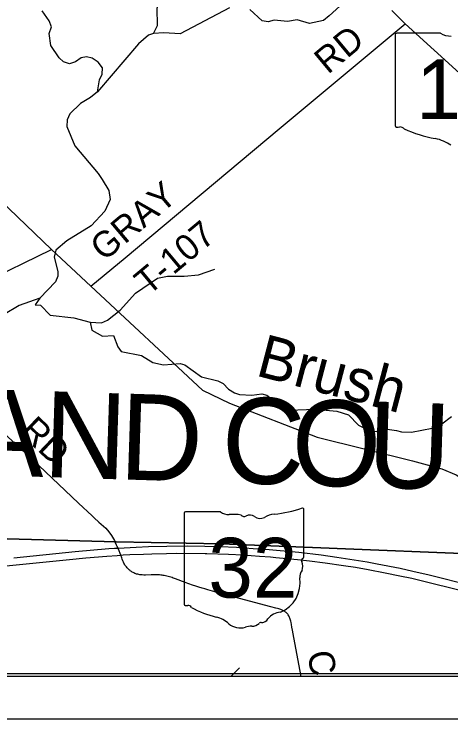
# Model space of a CAD drawing. Extents: x 0 to 34, y 0 to 22.
# Drawn here: x 3.558 to 4.521, y 14 to 15.554 of the extents above; entities that cross this region are included whole.
import ezdxf

# ---------------------------------------------------------------- set-up
doc = ezdxf.new("R2010")
doc.units = 0
for name, color, linetype in [('Default', 7, 'Continuous'), ('GM_X_County_Text', 7, 'Continuous'), ('GM_X_Minor_River', 7, 'Continuous'), ('GM_X_Minor_River_Text', 7, 'Continuous'), ('GM_X_State_Location', 7, 'Continuous'), ('GM_X_State_Route', 7, 'Continuous'), ('GM_X_State_Shield', 7, 'Continuous'), ('GM_X_Township_Road', 7, 'Continuous'), ('GM_X_Township_Road_Text', 7, 'Continuous'), ('SH_Cut_Line', 7, 'Continuous'), ('SH_Data', 7, 'Continuous')]:
    doc.layers.add(name, color=color, linetype=linetype)

msp = doc.modelspace()

# ---------------------------------------------------------------- linework, layer by layer
at = {"layer": 'Default'}
msp.add_lwpolyline([(2.3212, 18.6531), (2.2797, 17.8302), (2.2668, 17.0936), (2.2632, 16.8811), (2.258, 16.7775), (2.1837, 15.746), (2.1, 14.637), (2.1, 14.4457), (2.4012, 14.4298), (2.4436, 14.4284), (2.5802, 14.4232), (3.783, 14.3901), (4.0144, 14.3862), (4.819, 14.3535), (4.9366, 14.3421), (5.2368, 14.8438), (5.4205, 15.1508), (5.9071, 15.964)], dxfattribs=at)
msp.add_lwpolyline([(2.1, 14.4457), (2.1, 14.243), (2.102, 14.2411), (2.1319, 14.2168), (2.1359, 14.2103), (2.1425, 14.1753), (2.1455, 14.1482), (2.1436, 14.1288), (2.1399, 14.114), (2.1382, 14.1043), (2.1342, 14.0941), (7.3096, 14.0941), (7.3204, 14.3032), (6.8864, 14.3056), (6.7418, 14.3069), (5.4793, 14.3187), (5.0616, 14.3309), (4.9366, 14.3421), (4.819, 14.3535), (4.0144, 14.3862), (3.783, 14.3901), (2.5802, 14.4232), (2.4436, 14.4284), (2.4012, 14.4298)], close=True, dxfattribs=at)
at = {"layer": 'GM_X_Minor_River'}
for points in [[(3.8652, 15.5114), (3.8742, 15.5291), (3.8735, 15.5674), (3.8875, 15.6149), (3.8984, 15.6641), (3.9138, 15.6855), (3.9254, 15.6982), (3.9309, 15.7114), (3.9227, 15.7778), (3.9304, 15.7906), (3.9449, 15.798), (3.9692, 15.8226), (4.0016, 15.8385), (4.015, 15.8436)], [(4.276, 15.5716), (4.2526, 15.55), (4.2396, 15.5399), (4.2091, 15.5332), (4.1819, 15.5416), (4.1603, 15.5377), (4.1315, 15.5408), (4.1178, 15.5372), (4.1049, 15.5389), (4.0772, 15.564)], [(4.0329, 15.5681), (3.924, 15.5105), (3.888, 15.5129), (3.8652, 15.5114), (3.8541, 15.5077), (3.8319, 15.4884), (3.7417, 15.3823), (3.7267, 15.37), (3.7045, 15.3567), (3.681, 15.3339), (3.6748, 15.3207), (3.6742, 15.306), (3.6922, 15.2636), (3.743, 15.2022), (3.7523, 15.1891), (3.7671, 15.165), (3.7695, 15.1453), (3.7582, 15.1196), (3.7281, 15.0871), (3.6742, 15.0541), (3.65, 15.0336), (3.6463, 15.0181), (3.6543, 14.9861), (3.6545, 14.9762), (3.6494, 14.9634), (3.6147, 14.9279), (3.5694, 14.9114), (3.5346, 14.8907)], [(3.7417, 15.3823), (3.7464, 15.4094), (3.7523, 15.4214), (3.7529, 15.4354), (3.7429, 15.4481), (3.7298, 15.4567), (3.7177, 15.4599), (3.7055, 15.4575), (3.6932, 15.4486), (3.6799, 15.4443), (3.6671, 15.4491), (3.657, 15.4572), (3.6389, 15.4845), (3.6355, 15.5115), (3.6403, 15.5258), (3.6356, 15.5395), (3.6201, 15.5614)], [(3.6147, 14.9279), (3.6043, 14.9132), (3.6164, 14.9123), (3.6378, 14.8904), (3.6893, 14.8843), (3.7256, 14.8751), (3.7506, 14.8736), (3.7636, 14.8791), (3.7916, 14.9014), (3.8258, 14.9385), (3.8741, 14.9719), (3.8962, 14.9761), (3.933, 14.9764), (3.9645, 14.9789), (4.0003, 14.9917)], [(3.7256, 14.8751), (3.7291, 14.8572), (3.7525, 14.8439), (3.7768, 14.8451), (3.7867, 14.8207), (3.7941, 14.8103), (3.8387, 14.801), (3.864, 14.7858), (3.8874, 14.7809), (3.9242, 14.7834), (3.9341, 14.781), (3.9713, 14.7539), (4.0068, 14.7454), (4.0189, 14.7395), (4.0308, 14.7269), (4.0436, 14.7187), (4.0546, 14.7155), (4.0819, 14.714), (4.1039, 14.7167), (4.1149, 14.7139), (4.1505, 14.6864), (4.1641, 14.6805), (4.2218, 14.6831), (4.2691, 14.6782), (4.2952, 14.6702), (4.3173, 14.6479), (4.3406, 14.6362), (4.3557, 14.6337), (4.3752, 14.6394), (4.4005, 14.6356), (4.4115, 14.6332), (4.4342, 14.6321), (4.4795, 14.6413), (4.5008, 14.6508), (4.5219, 14.6668)], [(4.0364, 14.0941), (4.0453, 14.1028), (4.0549, 14.1129)]]:
    msp.add_lwpolyline(points, dxfattribs=at)
at = {"layer": 'GM_X_State_Route'}
for points in [[(5.4443, 14.4648), (5.2846, 14.7184), (5.2371, 14.8433), (5.0427, 14.9665), (4.4202, 15.5326), (4.3908, 15.5621)], [(3.5576, 14.3555), (3.6924, 14.369), (3.7667, 14.3756), (3.779, 14.3764), (3.787, 14.3768), (3.8002, 14.3775), (3.827, 14.3788), (3.8543, 14.38), (3.8948, 14.3809), (3.9396, 14.3813), (3.9781, 14.3808), (4.0125, 14.38), (4.0483, 14.3784), (4.0846, 14.3758), (4.1202, 14.3732), (4.1859, 14.3673), (4.2347, 14.3616), (4.2693, 14.3569), (4.2976, 14.3525), (4.3362, 14.3461), (4.3581, 14.3421), (4.4087, 14.332), (4.4366, 14.326), (4.4729, 14.3177), (4.5025, 14.3105), (4.5368, 14.3017)], [(3.496, 14.3328), (3.5627, 14.3397), (3.6066, 14.3441), (3.6802, 14.3514), (3.7161, 14.355), (3.7623, 14.3589), (3.7854, 14.3606), (3.7929, 14.361), (3.7987, 14.3614), (3.8134, 14.3622), (3.8432, 14.3635), (3.8612, 14.3643), (3.8942, 14.365), (3.9165, 14.3651), (3.9788, 14.3647)], [(3.9788, 14.3647), (3.9828, 14.3647), (4.0307, 14.3631), (4.0618, 14.3614), (4.0991, 14.3591), (4.1233, 14.3572), (4.1351, 14.3562), (4.1827, 14.3516), (4.2093, 14.3487), (4.2438, 14.3441), (4.2838, 14.3385), (4.3102, 14.3343), (4.3384, 14.3294), (4.3756, 14.3223), (4.4085, 14.3158), (4.4346, 14.3101), (4.4643, 14.3031), (4.5384, 14.2845)]]:
    msp.add_lwpolyline(points, dxfattribs=at)
at = {"layer": 'GM_X_State_Shield'}
for p, q in [((4.4978, 15.5118), (4.4013, 15.5118)), ((4.398, 15.5084), (4.398, 15.3082)), ((3.933, 14.4534), (3.933, 14.2532)), ((4.0128, 14.4568), (3.9355, 14.4568)), ((4.1966, 14.3571), (4.1966, 14.4618)), ((4.1966, 14.3571), (4.1966, 14.3571))]:
    msp.add_line(p, q, dxfattribs=at)
for centre, radius, start, end in [((3.936, 14.4538), 0.00305, 98.1301, 188.1301), ((4.0312, 14.48), 0.0296, 231.6195, 271.1119), ((4.1027, 14.7296), 0.2796, 275.8445, 288.9065), ((4.1937, 14.4622), 0.00294, 351.8621, 97.738), ((4.041, 14.3445), 0.1064, 80.4867, 94.9883), ((4.0651, 14.4548), 0.00855, 219.7921, 297.1024), ((4.0777, 14.4317), 0.0178, 54.4667, 119.1411), ((4.1006, 14.4634), 0.0214, 233.8562, 294.8282), ((4.1384, 14.3957), 0.0563, 97.3462, 120.7689), ((4.1959, 14.3494), 0.00454, 107.944, 210.337), ((4.167, 14.3362), 0.0273, 340.033, 23.6496), ((4.1935, 14.3567), 0.00314, 289.6038, 7.7341), ((4.2071, 14.3133), 0.0198, 136.8065, 186.9296), ((4.1184, 14.3), 0.0699, 292.3089, 8.9858), ((3.936, 14.2528), 0.00308, 171.9584, 258.3066), ((3.9365, 14.2733), 0.0235, 267.339, 280.6039), ((3.9413, 14.2417), 0.00848, 29.7484, 93.2717), ((4.0483, 14.4215), 0.2019, 240.4129, 257.1985), ((4.1479, 14.1971), 0.0383, 94.4031, 142.5768), ((3.9881, 14.1633), 0.0632, 47.1842, 75.836), ((4.0993, 14.2338), 0.0226, 282.8732, 323.2771), ((4.0565, 14.2407), 0.0401, 230.7004, 286.2918), ((4.0796, 14.1715), 0.0329, 85.6951, 111.2099), ((4.0826, 14.2257), 0.0214, 268.777, 315.5493), ((4.1019, 14.2063), 0.00601, 65.7517, 132.6484)]:
    msp.add_arc(centre, radius, start, end, dxfattribs=at)
for centre, major_axis, start_param, end_param in [((4.4018, 15.5088), (0.00382, 0), 1.712693, 3.28349), ((4.5208, 15.535), (0.037, 0), 4.042523, 4.731795), ((4.4019, 15.3078), (0.00385, 0), 3.00124, 4.508301), ((4.4024, 15.3283), (0.0294, 0), 4.665946, 4.897461), ((4.4085, 15.2967), (0.0106, 0), 0.519207, 1.627899), ((4.5423, 15.4765), (0.2524, 0), 4.195997, 4.488961), ((4.467, 15.2183), (0.079, 0), 0.823519, 1.323587)]:
    msp.add_ellipse(centre, major_axis=major_axis, ratio=0.8, start_param=start_param, end_param=end_param, dxfattribs=at)
at = {"layer": 'GM_X_Township_Road'}
msp.add_line((3.6407, 15.0353), (3.7273, 14.9544), dxfattribs=at)
for points in [[(3.1089, 15.5997), (3.1076, 15.5982), (3.1001, 15.5922), (3.0941, 15.5874), (3.0864, 15.5796), (3.0829, 15.5732), (3.0824, 15.5695), (3.0899, 15.5602), (3.2729, 15.3876), (3.4334, 15.2332), (3.6407, 15.0353)], [(3.7273, 14.9544), (3.8025, 15.0169), (4.1423, 15.3007), (4.4202, 15.5326)], [(2.5609, 14.9423), (2.8396, 14.8806), (2.9351, 14.891), (2.9697, 14.8931), (3.0011, 14.9073), (3.0233, 14.9153), (3.0404, 14.915), (3.1265, 14.9063), (3.1489, 14.9066), (3.2701, 14.9322), (3.3601, 14.9452), (3.3946, 14.9501), (3.4676, 14.9541), (3.4863, 14.9603), (3.6407, 15.0353)], [(3.7273, 14.9544), (3.9731, 14.7245), (4.0329, 14.6961), (4.2259, 14.6215), (4.436, 14.5692), (4.5009, 14.5517), (4.5325, 14.5378), (4.78, 14.3773), (4.8192, 14.353)], [(3.3721, 14.7809), (3.3742, 14.7789), (3.377, 14.776), (3.505, 14.6573), (3.5641, 14.6039), (3.6123, 14.559), (3.7002, 14.4758), (3.7297, 14.448)], [(3.7297, 14.448), (3.7346, 14.4434), (3.7446, 14.434), (3.76, 14.4204), (3.7668, 14.4124), (3.7726, 14.4046), (3.7789, 14.3931), (3.7807, 14.3896)], [(3.7929, 14.361), (3.788, 14.3743), (3.787, 14.3768), (3.7853, 14.3798), (3.7837, 14.3832), (3.7807, 14.3896)], [(3.9086, 14.3106), (3.9061, 14.3115), (3.9035, 14.3124), (3.9007, 14.3133), (3.8974, 14.3142), (3.8945, 14.315), (3.8918, 14.3155), (3.889, 14.3161), (3.8867, 14.3165), (3.884, 14.3169), (3.8812, 14.3171), (3.8788, 14.3173), (3.8754, 14.3174), (3.8728, 14.3175), (3.8694, 14.3175), (3.8655, 14.3174), (3.8599, 14.3174), (3.8475, 14.3171), (3.8438, 14.3172), (3.84, 14.3174), (3.8374, 14.3175), (3.8348, 14.3178), (3.8326, 14.3183), (3.8304, 14.3188), (3.828, 14.3193), (3.8263, 14.32), (3.824, 14.3209), (3.8221, 14.3217), (3.8202, 14.3227), (3.8185, 14.3236), (3.8166, 14.3248), (3.8151, 14.3259), (3.814, 14.3267), (3.8128, 14.3278), (3.8116, 14.3289), (3.8102, 14.3302), (3.8087, 14.3317), (3.807, 14.3334), (3.8055, 14.3351), (3.8041, 14.3368), (3.8023, 14.3391), (3.8011, 14.341), (3.7999, 14.3432), (3.7988, 14.3455), (3.7975, 14.3488), (3.7962, 14.3522), (3.7952, 14.3549), (3.7929, 14.361)], [(4.1903, 14.0941), (4.1897, 14.0971), (4.1727, 14.1874), (4.1714, 14.1955), (4.1703, 14.2023), (4.1694, 14.2079), (4.1685, 14.2127), (4.1679, 14.2155), (4.1672, 14.2179), (4.1666, 14.2201), (4.166, 14.2221), (4.1652, 14.2239), (4.1644, 14.2257), (4.1635, 14.2273), (4.1623, 14.2292), (4.161, 14.231), (4.1597, 14.2326), (4.1578, 14.2343), (4.1561, 14.2356), (4.1545, 14.2368), (4.1531, 14.2377), (4.1515, 14.2386), (4.15, 14.2393), (4.1477, 14.2403), (4.1457, 14.2411), (4.1436, 14.2418), (4.1411, 14.2425), (4.1382, 14.2434), (4.1346, 14.2444), (4.1239, 14.2471), (4.0765, 14.2596), (4.0467, 14.2676), (3.9953, 14.2818), (3.9851, 14.2846), (3.9782, 14.2865), (3.9724, 14.2883), (3.9653, 14.2905), (3.9588, 14.2927), (3.9515, 14.2952), (3.9352, 14.3009), (3.9134, 14.3088), (3.9094, 14.3103), (3.9086, 14.3106)]]:
    msp.add_lwpolyline(points, dxfattribs=at)
at = {"layer": 'SH_Cut_Line'}
msp.add_lwpolyline([(2.3212, 18.6531), (2.2797, 17.8302), (2.2668, 17.0936), (2.2632, 16.8811), (2.258, 16.7775), (2.1837, 15.746), (2.1, 14.637), (2.1, 14.4457), (2.4012, 14.4298), (2.4436, 14.4284), (2.5802, 14.4232), (3.783, 14.3901), (4.0144, 14.3862), (4.819, 14.3535), (4.9366, 14.3421), (5.0616, 14.3309), (5.4793, 14.3187), (6.7418, 14.3069), (6.8864, 14.3056), (7.3204, 14.3032), (8.6074, 14.2911), (8.7041, 14.2905), (8.9, 14.2922), (8.9, 20.8941)], dxfattribs=at)
at = {"layer": 'SH_Data'}
for p, q in [((2.1, 14.1), (8.9, 14.1)), ((2, 14), (9, 14))]:
    msp.add_line(p, q, dxfattribs=at)

# ---------------------------------------------------------------- texts
at = {"layer": 'GM_X_County_Text'}
for s, rotation, p in [('A', 358.1957, (3.4533, 14.5388)), ('N', 358.1946, (3.6207, 14.5335)), ('D', 358.1957, (3.7882, 14.5283)), ('C', 358.1954, (4.013, 14.5212)), ('O', 358.1946, (4.1671, 14.5163)), ('U', 358.1946, (4.3345, 14.511))]:
    msp.add_text(s, height=0.1894, rotation=rotation, dxfattribs=at).set_placement(p)
at = {"layer": 'GM_X_Minor_River_Text'}
msp.add_text('Brush', height=0.09466, rotation=345.3149, dxfattribs=at).set_placement((4.0879, 14.7577))
at = {"layer": 'GM_X_State_Location'}
for s, p in [('134', (4.4923, 15.3812)), ('32', (4.0141, 14.3262))]:
    msp.add_text(s, height=0.000189, rotation=0, dxfattribs=at).set_placement(p)
for s in ['s', 'r']:
    msp.add_text(s, height=0.000189, dxfattribs=at).set_placement((4.0618, 14.34))
at = {"layer": 'GM_X_State_Shield'}
for s, p in [('134', (4.4446, 15.3224)), ('32', (3.9861, 14.2674))]:
    msp.add_text(s, height=0.13184, dxfattribs=at).set_placement(p)
at = {"layer": 'GM_X_Township_Road_Text'}
for s, height, rotation, p in [('RD', 0.05682, 39.741, (4.2497, 15.4198)), ('GRAY', 0.05682, 40.0228, (3.7562, 15.0072)), ('T-107', 0.05682, 39.8415, (3.8538, 14.9319)), ('RD', 0.05682, 316.4027, (3.5678, 14.631)), ('C', 0.0568, 281.0352, (4.2036, 14.1452))]:
    msp.add_text(s, height=height, rotation=rotation, dxfattribs=at).set_placement(p)

doc.saveas('drawing.dxf')
